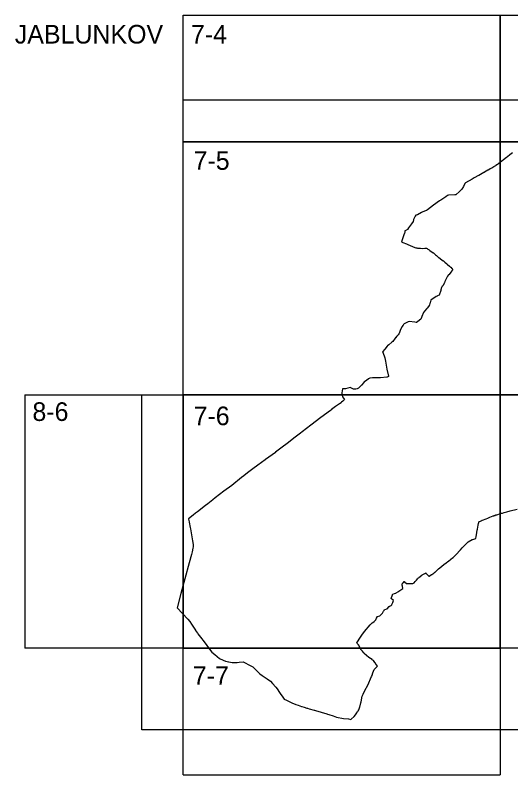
# Model space of a CAD drawing. Extents: x -449577 to -436680, y -1132317 to -1125726.
# Drawn here: x -441794.4 to -441550, y -1130325 to -1129950 of the extents above; entities that cross this region are included whole.
import ezdxf

# ---------------------------------------------------------------- set-up
doc = ezdxf.new("R2010")
doc.units = 0
for name, color, linetype in [('Vrstva 1', 7, 'Continuous'), ('Vrstva 10', 7, 'Continuous'), ('Vrstva 4', 7, 'Continuous')]:
    doc.layers.add(name, color=color, linetype=linetype)

msp = doc.modelspace()

# ---------------------------------------------------------------- linework, layer by layer
at = {"layer": 'Vrstva 1'}
for points in [[(-441549.24, -1130018), (-441550.45, -1130018.96), (-441550.45, -1130018.96), (-441551.6, -1130019.83), (-441552.17, -1130020.26), (-441552.75, -1130020.7), (-441552.91, -1130020.82), (-441555.04, -1130022.46), (-441556.11, -1130023.28), (-441556.58, -1130023.62), (-441557.34, -1130024.13), (-441557.59, -1130024.29), (-441558.18, -1130024.68), (-441558.22, -1130024.71), (-441558.43, -1130024.85), (-441559.34, -1130025.45), (-441559.35, -1130025.45), (-441559.82, -1130025.71), (-441559.97, -1130025.79), (-441560.15, -1130025.89), (-441560.61, -1130026.14), (-441560.79, -1130026.25), (-441560.95, -1130026.34), (-441561.05, -1130026.4), (-441561.29, -1130026.54), (-441562.95, -1130027.48), (-441563.12, -1130027.57), (-441563.35, -1130027.7), (-441565.82, -1130029.1), (-441565.94, -1130029.17), (-441568.05, -1130030.3), (-441569.07, -1130030.85), (-441572.41, -1130032.66), (-441572.58, -1130032.96), (-441572.64, -1130033.07), (-441573.42, -1130034.53), (-441574.1, -1130035.85), (-441574.24, -1130035.98), (-441574.33, -1130036.06), (-441575.47, -1130037.1), (-441576.98, -1130038.48), (-441577.15, -1130038.63), (-441577.15, -1130038.64), (-441577.62, -1130038.65), (-441580.81, -1130038.74), (-441580.82, -1130038.74), (-441581.25, -1130039.03), (-441582.08, -1130039.6), (-441584.55, -1130041.26), (-441584.59, -1130041.28), (-441584.83, -1130041.46), (-441585.1, -1130041.66), (-441588.08, -1130043.79), (-441588.15, -1130043.84), (-441591.15, -1130046.02), (-441591.62, -1130046.36), (-441591.78, -1130046.42), (-441593.72, -1130047.14), (-441593.73, -1130047.14), (-441594.12, -1130047.38), (-441596, -1130048.54), (-441596.92, -1130048.75), (-441597.17, -1130049.26), (-441597.93, -1130050.77), (-441597.94, -1130050.78), (-441598.01, -1130051.04), (-441598.21, -1130051.88), (-441599.04, -1130052.99), (-441600.41, -1130054.94), (-441600.97, -1130055.75), (-441601, -1130055.77), (-441602.16, -1130056.41), (-441602.26, -1130056.47), (-441602.33, -1130056.86), (-441602.48, -1130057.67), (-441602.53, -1130057.86), (-441603.82, -1130061.44), (-441603.99, -1130061.92), (-441603.96, -1130061.91), (-441603.94, -1130061.9), (-441603.26, -1130062.16), (-441601.45, -1130062.82), (-441600.83, -1130063.11), (-441598.54, -1130064.19), (-441598.52, -1130064.19), (-441597.36, -1130064.66), (-441596.89, -1130064.84), (-441596.86, -1130064.85), (-441596.43, -1130064.88), (-441596.29, -1130064.89), (-441596.07, -1130064.91), (-441594.47, -1130065.01), (-441593.43, -1130065.08), (-441592.38, -1130065.05), (-441591.54, -1130065.02), (-441591.53, -1130065.02), (-441591.25, -1130065.17), (-441590.88, -1130065.43), (-441590.33, -1130065.81), (-441589.94, -1130066.09), (-441588.38, -1130067.23), (-441588.21, -1130067.35), (-441587.1, -1130068.27), (-441586.71, -1130068.59), (-441586.53, -1130068.74), (-441585.78, -1130069.35), (-441585.51, -1130069.58), (-441584.91, -1130070.07), (-441584.69, -1130070.25), (-441584.05, -1130070.67), (-441583.3, -1130071.17), (-441583.27, -1130071.19), (-441582.51, -1130071.87), (-441581.63, -1130072.65), (-441581.19, -1130073.03), (-441580.18, -1130073.92), (-441579.92, -1130074.15), (-441579.87, -1130074.2), (-441579.77, -1130074.3), (-441579.76, -1130074.31), (-441579.67, -1130074.41), (-441579.64, -1130074.44), (-441578.59, -1130075.67), (-441578.6, -1130075.68), (-441579.04, -1130076.17), (-441579.1, -1130076.24), (-441579.67, -1130076.87), (-441580.49, -1130077.93), (-441580.66, -1130078.14), (-441581.22, -1130078.86), (-441581.52, -1130079.39), (-441581.54, -1130079.43), (-441581.55, -1130079.45), (-441581.68, -1130079.73), (-441582.48, -1130081.4), (-441582.79, -1130082.04), (-441583.41, -1130083.33), (-441583.52, -1130083.57), (-441583.53, -1130083.57), (-441583.57, -1130083.6), (-441583.86, -1130083.8), (-441583.94, -1130083.84), (-441583.99, -1130083.94), (-441584.08, -1130084.14), (-441584.17, -1130084.42), (-441584.34, -1130084.98), (-441584.35, -1130085), (-441584.47, -1130085.5), (-441584.49, -1130085.57), (-441584.48, -1130085.63), (-441584.47, -1130085.71), (-441584.47, -1130085.78), (-441584.48, -1130085.83), (-441585.36, -1130088.16), (-441585.38, -1130088.21), (-441585.4, -1130088.25), (-441585.41, -1130088.26), (-441586.11, -1130088.56), (-441586.36, -1130088.67), (-441586.83, -1130088.91), (-441589.44, -1130090.6), (-441589.44, -1130090.6), (-441589.81, -1130091.91), (-441589.89, -1130092.17), (-441590, -1130092.59), (-441590.06, -1130092.8), (-441590.06, -1130092.81), (-441590.05, -1130092.81), (-441589.88, -1130092.97), (-441589.89, -1130092.98), (-441590.25, -1130093.37), (-441591.05, -1130094.37), (-441591.06, -1130094.38), (-441591.27, -1130094.63), (-441591.27, -1130094.64), (-441591.39, -1130094.79), (-441592.55, -1130096.14), (-441593.09, -1130096.77), (-441593.85, -1130098.72), (-441594.23, -1130099.74), (-441594.36, -1130100.09), (-441595.89, -1130101.19), (-441596.51, -1130101.63), (-441596.69, -1130101.67), (-441596.71, -1130101.67), (-441597.34, -1130101.58), (-441600.18, -1130101.16), (-441600.67, -1130101.4), (-441602, -1130102.04), (-441602.54, -1130102.3), (-441602.57, -1130102.33), (-441603, -1130102.74), (-441603.17, -1130102.96), (-441603.83, -1130103.81), (-441603.83, -1130103.82), (-441604.5, -1130105.62), (-441605.07, -1130107.12), (-441605.07, -1130107.12), (-441605.21, -1130107.34), (-441605.54, -1130107.71), (-441606.26, -1130108.51), (-441606.96, -1130109.28), (-441606.97, -1130109.3), (-441607.1, -1130109.49), (-441608.17, -1130111.06), (-441608.64, -1130111.44), (-441610.21, -1130112.7), (-441610.88, -1130113.24), (-441610.98, -1130113.32), (-441611.01, -1130113.36), (-441612.13, -1130114.79), (-441613.27, -1130116.1), (-441613.12, -1130116.27), (-441613.11, -1130116.3), (-441613.11, -1130116.31), (-441612.1, -1130119.07), (-441611.82, -1130120.73), (-441611.5, -1130122.68), (-441611.09, -1130124.64), (-441610.36, -1130128.14), (-441610.32, -1130128.34), (-441610.97, -1130128.68), (-441611.09, -1130128.75), (-441614.26, -1130129.01), (-441614.42, -1130129.01), (-441615.91, -1130128.98), (-441618.3, -1130128.96), (-441619.58, -1130129.23), (-441620.18, -1130129.5), (-441621.16, -1130130.3), (-441622.46, -1130131.17), (-441622.55, -1130131.28), (-441623.71, -1130132.7), (-441625.16, -1130134.04), (-441625.85, -1130134.36), (-441626.45, -1130134.64), (-441627.62, -1130134.57), (-441629.23, -1130133.72), (-441631.47, -1130134.39), (-441632.95, -1130134.36), (-441633.33, -1130136.47), (-441633.34, -1130136.49), (-441633.35, -1130136.58), (-441633.06, -1130138.39), (-441632.09, -1130139.71), (-441632.08, -1130139.73), (-441632.82, -1130140.48), (-441633.43, -1130141.04), (-441633.68, -1130141.27), (-441634.48, -1130141.9), (-441636.41, -1130143.13), (-441636.47, -1130143.17), (-441638.44, -1130144.7), (-441638.5, -1130144.74), (-441638.99, -1130145.12), (-441643.65, -1130148.58), (-441643.68, -1130148.61), (-441648.63, -1130152.37), (-441652.89, -1130155.62), (-441653.77, -1130156.28), (-441656.34, -1130158.22), (-441660.34, -1130161.35), (-441662.78, -1130163.22), (-441666.09, -1130165.75), (-441666.14, -1130165.79), (-441670.93, -1130169.3), (-441671.16, -1130169.48), (-441674.77, -1130172.16), (-441677.16, -1130173.98), (-441679.13, -1130175.46), (-441681.45, -1130177.21), (-441681.68, -1130177.38), (-441682.81, -1130178.27), (-441687.63, -1130182.07), (-441691.52, -1130185.02), (-441695.74, -1130188.27), (-441697.03, -1130189.27), (-441699.42, -1130191.15), (-441700.6, -1130192.07), (-441704.54, -1130195.12), (-441705.47, -1130195.83), (-441706.71, -1130196.79), (-441709.03, -1130198.59), (-441709.03, -1130198.59), (-441708.99, -1130198.77), (-441708.7, -1130200.15), (-441708.67, -1130200.31), (-441708.14, -1130202.85), (-441707.98, -1130203.58), (-441707.98, -1130203.62), (-441707.05, -1130209.5), (-441707.04, -1130209.53), (-441706.74, -1130211.26), (-441706.74, -1130211.28), (-441706.68, -1130211.65), (-441706.62, -1130212.07), (-441706.65, -1130212.44), (-441706.8, -1130213.17), (-441707.18, -1130214.96), (-441707.47, -1130216.14), (-441707.49, -1130216.19), (-441708.6, -1130220.36), (-441710.7, -1130228.24), (-441712.69, -1130235.46), (-441714.62, -1130242.56), (-441714.63, -1130242.6), (-441709.35, -1130248.2), (-441708.3, -1130249.33), (-441707.54, -1130250.55), (-441705.52, -1130253.61), (-441705.47, -1130253.68), (-441704.46, -1130255.09), (-441704.3, -1130255.3), (-441702.42, -1130257.78), (-441701.85, -1130258.52), (-441701.82, -1130258.56), (-441701.3, -1130259.28), (-441699.92, -1130261.18), (-441699.59, -1130261.63), (-441697.44, -1130264.35), (-441696.04, -1130265.57), (-441693.64, -1130267.55), (-441691.9, -1130268.3), (-441690.71, -1130268.82), (-441690.58, -1130268.87), (-441689.25, -1130269.15), (-441689.11, -1130269.18), (-441687.49, -1130269.51), (-441687.46, -1130269.51), (-441686.5, -1130269.49), (-441686.12, -1130269.49), (-441685.6, -1130269.48), (-441684.92, -1130269.47), (-441684.01, -1130269.43), (-441682.06, -1130269.27), (-441681.61, -1130269.34), (-441680.95, -1130269.69), (-441679.23, -1130270.64), (-441677.27, -1130271.74), (-441676.75, -1130272.22), (-441676.03, -1130272.9), (-441675.23, -1130273.65), (-441673.91, -1130274.95), (-441673.77, -1130275.05), (-441672.58, -1130275.9), (-441670.17, -1130277.61), (-441668.53, -1130278.79), (-441667.48, -1130279.97), (-441665.84, -1130281.79), (-441665.2, -1130282.5), (-441664.84, -1130283.09), (-441664.38, -1130283.83), (-441663.44, -1130285.3), (-441662.81, -1130286.22), (-441661.77, -1130287.66), (-441660.7, -1130288.17), (-441659.32, -1130288.82), (-441658.01, -1130289.43), (-441656.04, -1130290.32), (-441654.91, -1130290.67), (-441653.19, -1130291.24), (-441653.04, -1130291.29), (-441651.95, -1130291.61), (-441650.53, -1130292.03), (-441650.52, -1130292.03), (-441650.31, -1130292.09), (-441650.25, -1130292.11), (-441649.39, -1130292.37), (-441647, -1130293.06), (-441646.88, -1130293.1), (-441646.4, -1130293.24), (-441643.47, -1130294.11), (-441640.78, -1130294.94), (-441640.44, -1130295.04), (-441639.68, -1130295.27), (-441637.67, -1130295.89), (-441635.94, -1130296.44), (-441632.48, -1130297.18)], [(-441632.48, -1130297.18), (-441630.09, -1130297.37), (-441628.89, -1130297.6), (-441628.78, -1130297.51), (-441627.2, -1130296.24), (-441626.17, -1130294.76), (-441626.06, -1130294.61), (-441625.54, -1130293.85), (-441625.43, -1130293.68), (-441625.29, -1130293.45), (-441624.91, -1130292.82), (-441624.64, -1130291.99), (-441624.62, -1130291.92), (-441624.6, -1130291.87), (-441624.57, -1130291.76), (-441624.54, -1130291.67), (-441624.54, -1130291.66), (-441623.91, -1130289.46), (-441623.77, -1130288.94), (-441623.32, -1130286.19), (-441623.32, -1130286.19), (-441623.13, -1130285.75), (-441622.87, -1130285.13), (-441622.08, -1130283.3), (-441620.51, -1130280.65), (-441618.76, -1130276.52), (-441618.44, -1130275.88), (-441618.4, -1130275.75), (-441618.01, -1130274.65), (-441617.42, -1130272.98), (-441615.74, -1130271.27), (-441616.67, -1130270.03), (-441616.73, -1130269.94), (-441616.78, -1130269.88), (-441616.81, -1130269.84), (-441616.88, -1130269.74), (-441616.93, -1130269.66), (-441617.01, -1130269.54), (-441617.37, -1130269.02), (-441617.74, -1130268.56), (-441618.31, -1130268.19), (-441618.41, -1130268.13), (-441620.06, -1130267.06), (-441622.25, -1130265.12), (-441622.38, -1130264.95), (-441622.41, -1130264.91), (-441622.49, -1130264.81), (-441622.83, -1130264.39), (-441623.16, -1130263.98), (-441623.42, -1130263.66), (-441623.9, -1130263.07), (-441623.98, -1130262.97), (-441624.48, -1130262.01), (-441624.77, -1130261.45), (-441625, -1130261.02), (-441625.05, -1130260.93), (-441625.09, -1130260.88), (-441625.35, -1130260.59), (-441625.55, -1130260.36), (-441625.81, -1130260.07), (-441626.03, -1130259.82), (-441624.17, -1130257.08), (-441624.08, -1130256.96), (-441623.76, -1130256.51), (-441623.44, -1130256.07), (-441622.11, -1130254.24), (-441619.43, -1130250.98), (-441619.08, -1130250.66), (-441618.37, -1130249.96), (-441618.26, -1130249.87), (-441618.07, -1130249.73), (-441617.47, -1130249.25), (-441616.61, -1130248.41), (-441616.2, -1130247.65), (-441615.73, -1130246.78), (-441614.68, -1130246.54), (-441613.28, -1130245.11), (-441612.74, -1130244.26), (-441612.73, -1130244.25), (-441612.73, -1130244.23), (-441612.52, -1130243.9), (-441612.47, -1130243.82), (-441612.23, -1130243.43), (-441611.07, -1130242.99), (-441610.05, -1130241.81), (-441609.52, -1130241.61), (-441609.4, -1130241.56), (-441608.98, -1130241.4), (-441608.76, -1130241.01), (-441608.71, -1130240.92), (-441608.54, -1130240.62), (-441608.13, -1130239.88), (-441607.93, -1130238.97), (-441607.93, -1130238.95), (-441607.92, -1130238.94), (-441608.97, -1130237.95), (-441608.99, -1130237.94), (-441609, -1130237.92), (-441609.05, -1130237.88), (-441608.4, -1130236.08), (-441608.33, -1130235.88), (-441608.17, -1130235.82), (-441607.44, -1130235.53), (-441606.75, -1130235.26), (-441606.63, -1130235.21), (-441605.42, -1130234.5), (-441605.3, -1130234.42), (-441605.3, -1130234.42), (-441605.29, -1130234.41), (-441605.17, -1130234.34), (-441603.31, -1130232.94), (-441603.31, -1130232.9), (-441603.34, -1130232.74), (-441603.41, -1130232.26), (-441603.47, -1130231.91), (-441603.57, -1130231.29), (-441603.59, -1130231.18), (-441603.61, -1130231.05), (-441603.63, -1130230.88), (-441603.66, -1130230.74), (-441603.12, -1130230.18), (-441602.56, -1130229.61), (-441602.52, -1130229.56), (-441602.38, -1130229.66), (-441601.38, -1130230.45), (-441600.7, -1130230.46), (-441600.64, -1130230.46), (-441600.39, -1130230.47), (-441600.23, -1130230.47), (-441598.92, -1130230.49), (-441598.29, -1130230.51), (-441598.02, -1130230.35), (-441597.99, -1130230.33), (-441597.87, -1130230.26), (-441597.73, -1130230.17), (-441597.69, -1130230.14), (-441597.15, -1130229.54), (-441597.04, -1130229.42), (-441596.95, -1130229.32), (-441596.78, -1130229.14), (-441596.7, -1130229.05), (-441596.59, -1130228.93), (-441596.56, -1130228.89), (-441596.53, -1130228.86), (-441596.48, -1130228.8), (-441596.39, -1130228.69), (-441595.99, -1130228.19), (-441595.78, -1130227.93), (-441595.53, -1130227.61), (-441595.42, -1130227.53), (-441593.96, -1130226.46), (-441593.75, -1130226.33), (-441592.39, -1130225.56), (-441591.99, -1130225.33), (-441591.99, -1130225.33), (-441591.85, -1130225.48), (-441591.14, -1130226.19), (-441590.77, -1130226.57), (-441590.59, -1130226.74), (-441590.44, -1130226.89), (-441590.35, -1130226.85), (-441589.07, -1130226.08), (-441588.98, -1130226.03), (-441588.05, -1130225.47), (-441588.01, -1130225.44), (-441587.68, -1130225.15), (-441587.63, -1130225.11), (-441587.46, -1130224.96), (-441587.45, -1130224.95), (-441587.45, -1130224.95), (-441587.41, -1130224.91), (-441587.37, -1130224.87), (-441586.48, -1130224.06), (-441586.46, -1130224.05), (-441585.87, -1130223.51), (-441585.76, -1130223.42), (-441585.65, -1130223.32), (-441585.65, -1130223.32), (-441585.64, -1130223.32), (-441585.64, -1130223.32), (-441585.64, -1130223.31), (-441585.63, -1130223.31), (-441585.62, -1130223.3), (-441585.62, -1130223.3), (-441585.61, -1130223.29), (-441585.61, -1130223.29), (-441585.6, -1130223.29), (-441585.6, -1130223.29), (-441585.02, -1130222.8), (-441583.03, -1130221.12), (-441581.83, -1130220.27), (-441581.71, -1130220.19), (-441581.66, -1130220.15), (-441581.64, -1130220.14), (-441581.59, -1130220.11), (-441581.23, -1130219.84), (-441579.99, -1130218.9), (-441579.81, -1130218.76), (-441579.6, -1130218.6), (-441579.58, -1130218.58), (-441578.7, -1130217.91), (-441578.35, -1130217.64), (-441578.3, -1130217.58), (-441578.21, -1130217.48), (-441577.57, -1130216.8), (-441576.67, -1130215.82), (-441575.31, -1130214.41), (-441575.09, -1130214.18), (-441574.84, -1130213.9), (-441574, -1130212.95), (-441573.71, -1130212.63), (-441573.51, -1130212.42), (-441573.22, -1130212.1), (-441572.04, -1130210.91), (-441571.11, -1130209.89), (-441569.05, -1130208.88), (-441568.89, -1130208.83), (-441568.69, -1130208.75), (-441567.25, -1130208.26), (-441567.1, -1130207.39), (-441566.94, -1130206.52), (-441566.52, -1130204.15), (-441566.44, -1130203.68), (-441566.11, -1130201.8), (-441565.91, -1130200.92), (-441565.88, -1130200.8), (-441565.83, -1130200.61), (-441565.82, -1130200.57), (-441565.8, -1130200.5), (-441565.79, -1130200.46), (-441565.78, -1130200.41), (-441565.77, -1130200.37), (-441565.76, -1130200.35), (-441565.7, -1130200.14), (-441564.62, -1130199.6), (-441564.33, -1130199.46), (-441564.31, -1130199.45), (-441564.06, -1130199.32), (-441564.01, -1130199.3), (-441562.24, -1130198.58), (-441562.21, -1130198.57), (-441562.18, -1130198.55), (-441561.38, -1130198.24), (-441560.42, -1130197.84), (-441559.61, -1130197.5), (-441558.67, -1130197.11), (-441558.59, -1130197.08), (-441557.98, -1130196.84), (-441558.13, -1130197), (-441557.89, -1130196.91), (-441557.4, -1130196.71), (-441556.87, -1130196.55), (-441555.17, -1130196.03), (-441554.58, -1130195.86), (-441554.13, -1130195.74), (-441553.24, -1130195.49), (-441551.93, -1130195.11), (-441550.39, -1130194.65), (-441546.85, -1130193.78)]]:
    msp.add_lwpolyline(points, dxfattribs=at)
at = {"layer": 'Vrstva 10'}
msp.add_lwpolyline([(-441399.09, -1129991.79), (-441399.09, -1130302.77), (-441731.96, -1130302.77), (-441731.96, -1130137.47), (-441711.59, -1130137.47), (-441711.59, -1130012.47), (-441711.59, -1129991.79), (-441399.09, -1129991.79)], dxfattribs=at)
at = {"layer": 'Vrstva 4'}
for p, q in [((-441711.59, -1129949.97), (-441399.09, -1129949.97)), ((-441789.72, -1130137.47), (-441789.72, -1130262.47)), ((-441711.59, -1130324.97), (-441555.34, -1130324.97))]:
    msp.add_line(p, q, dxfattribs=at)
for points in [[(-441555.34, -1129949.97), (-441555.34, -1130012.47), (-441711.59, -1130012.47), (-441711.59, -1129949.97)], [(-441399.09, -1129949.97), (-441399.09, -1130012.47), (-441555.34, -1130012.47), (-441555.34, -1129949.97)], [(-441789.72, -1130137.47), (-441711.59, -1130137.47), (-441711.59, -1130262.47), (-441789.72, -1130262.47)], [(-441711.59, -1130324.97), (-441711.59, -1130262.47), (-441555.34, -1130262.47), (-441555.34, -1130324.97)]]:
    msp.add_lwpolyline(points, dxfattribs=at)
for points in [[(-441555.34, -1130012.47), (-441555.34, -1130137.47), (-441711.59, -1130137.47), (-441711.59, -1130012.47)], [(-441399.09, -1130012.47), (-441399.09, -1130137.47), (-441555.34, -1130137.47), (-441555.34, -1130012.47)], [(-441555.34, -1130137.47), (-441555.34, -1130262.47), (-441711.59, -1130262.47), (-441711.59, -1130137.47)], [(-441399.09, -1130137.47), (-441399.09, -1130262.47), (-441555.34, -1130262.47), (-441555.34, -1130137.47)]]:
    msp.add_lwpolyline(points, close=True, dxfattribs=at)

# ---------------------------------------------------------------- texts
at = {"layer": 'Vrstva 1'}
for s, p in [('JABLUNKOV', (-441794.63, -1129963.97)), ('7-4', (-441707.78, -1129963.97)), ('7-5', (-441706.47, -1130026.31)), ('8-6', (-441785.94, -1130150.28)), ('7-6', (-441706.47, -1130152.38)), ('7-7', (-441706.83, -1130280.55))]:
    msp.add_text(s, height=9.2, dxfattribs=at).set_placement(p)

doc.saveas('drawing.dxf')
